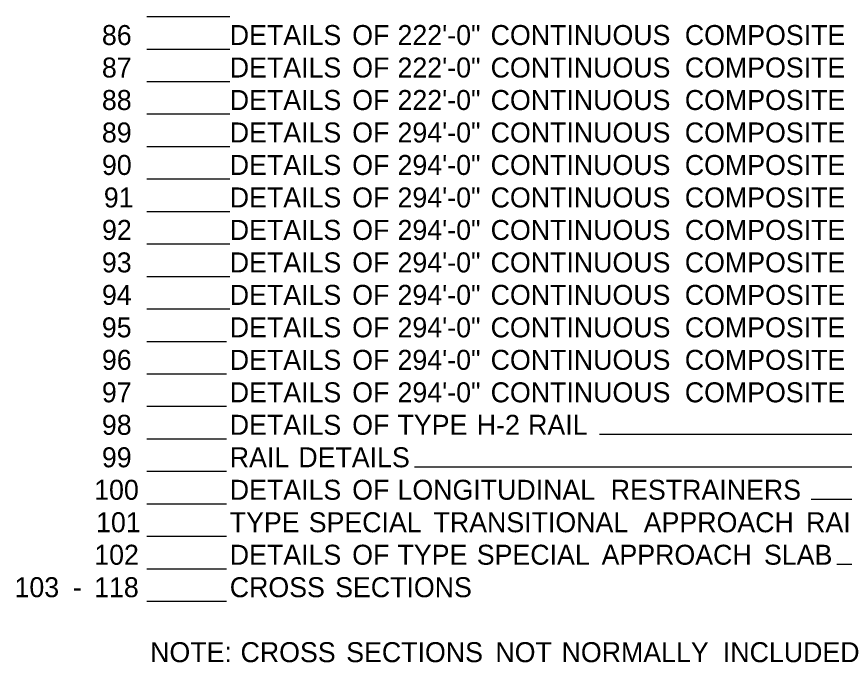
# Model space of a CAD drawing. Extents: x 2 to 32.9, y 0.7 to 21.4.
# Drawn here: x 2.06 to 8.57, y 1.03 to 6.11 of the extents above; entities that cross this region are included whole.
import ezdxf

# ---------------------------------------------------------------- set-up
doc = ezdxf.new("R2010")
doc.units = 0
doc.layers.add('Default', color=7, linetype='Continuous')

msp = doc.modelspace()

# ---------------------------------------------------------------- linework, layer by layer
at = {"layer": 'Default'}
for p, q in [((3.0822, 6.1118), (3.734, 6.1118)), ((3.0822, 5.8562), (3.734, 5.8562)), ((3.0822, 5.8562), (3.7084, 5.8562)), ((3.0822, 5.8562), (3.7084, 5.8562)), ((3.0822, 5.6006), (3.734, 5.6006)), ((3.0822, 5.6006), (3.7084, 5.6006)), ((3.0822, 5.6006), (3.7084, 5.6006)), ((3.0822, 5.3451), (3.734, 5.3451)), ((3.0822, 5.3451), (3.7084, 5.3451)), ((3.0822, 5.3451), (3.7084, 5.3451)), ((3.0822, 5.0895), (3.734, 5.0895)), ((3.0822, 5.0895), (3.7084, 5.0895)), ((3.0822, 5.0895), (3.7084, 5.0895)), ((3.0822, 4.8339), (3.734, 4.8339)), ((3.0822, 4.8339), (3.7084, 4.8339)), ((3.0822, 4.8339), (3.7084, 4.8339)), ((3.0822, 4.5783), (3.734, 4.5783)), ((3.0822, 4.5783), (3.7084, 4.5783)), ((3.0822, 4.5783), (3.7084, 4.5783)), ((3.0822, 4.3227), (3.734, 4.3227)), ((3.0822, 4.3227), (3.7084, 4.3227)), ((3.0822, 4.3227), (3.7084, 4.3227)), ((3.0822, 4.0671), (3.734, 4.0671)), ((3.0822, 4.0671), (3.7084, 4.0671)), ((3.0822, 4.0671), (3.7084, 4.0671)), ((3.0822, 3.8115), (3.734, 3.8115)), ((3.0822, 3.8115), (3.7084, 3.8115)), ((3.0822, 3.8115), (3.7084, 3.8115)), ((3.0822, 3.5559), (3.7084, 3.5559)), ((3.0822, 3.5559), (3.7084, 3.5559)), ((3.0822, 3.3003), (3.7084, 3.3003)), ((3.0822, 3.3003), (3.7084, 3.3003)), ((3.0822, 3.0447), (3.7084, 3.0447)), ((3.0822, 3.0447), (3.7084, 3.0447)), ((6.6412, 2.8243), (13.6355, 2.8243)), ((3.0822, 2.7892), (3.7084, 2.7892)), ((3.0822, 2.7892), (3.7084, 2.7892)), ((5.1864, 2.5687), (13.6355, 2.5687)), ((3.0822, 2.5336), (3.7084, 2.5336)), ((3.0822, 2.5336), (3.7084, 2.5336)), ((8.3055, 2.3131), (13.6355, 2.3131)), ((3.0822, 2.278), (3.7084, 2.278)), ((3.0822, 2.278), (3.7084, 2.278)), ((3.0822, 2.0224), (3.7084, 2.0224)), ((3.0822, 2.0224), (3.7084, 2.0224)), ((3.0822, 1.7668), (3.7084, 1.7668)), ((3.0822, 1.7668), (3.7084, 1.7668)), ((8.5089, 1.8019), (13.6355, 1.8019)), ((3.0822, 1.5112), (3.7084, 1.5112)), ((3.0822, 1.5112), (3.7084, 1.5112))]:
    msp.add_line(p, q, dxfattribs=at)

# ---------------------------------------------------------------- texts
for s, height, p in [('86', 0.15729, (2.7286, 5.8877)), ('86', 0.15729, (2.7286, 5.8877)), ('DETAILS', 0.15729, (3.734, 5.8877)), ('DETAILS', 0.15729, (3.734, 5.8877)), (' OF', 0.15729, (4.6385, 5.8877)), (' OF', 0.15729, (4.6385, 5.8877)), (' 222\'-0"', 0.15729, (4.9947, 5.8877)), (' 222\'-0"', 0.15729, (4.9947, 5.8877)), (' CONTINUOUS', 0.157286, (5.7271, 5.8877)), (' CONTINUOUS', 0.157286, (5.7271, 5.8877)), (' COMPOSITE', 0.15729, (7.2541, 5.8877)), (' COMPOSITE', 0.15729, (7.2541, 5.8877)), ('87', 0.15729, (2.7286, 5.6321)), ('87', 0.15729, (2.7286, 5.6321)), ('DETAILS', 0.15729, (3.734, 5.6321)), ('DETAILS', 0.15729, (3.734, 5.6321)), (' OF', 0.15729, (4.6385, 5.6321)), (' OF', 0.15729, (4.6385, 5.6321)), (' 222\'-0"', 0.15729, (4.9947, 5.6321)), (' 222\'-0"', 0.15729, (4.9947, 5.6321)), (' CONTINUOUS', 0.157286, (5.7271, 5.6321)), (' CONTINUOUS', 0.157286, (5.7271, 5.6321)), (' COMPOSITE', 0.15729, (7.2541, 5.6321)), (' COMPOSITE', 0.15729, (7.2541, 5.6321)), ('88', 0.15729, (2.7285, 5.3765)), ('88', 0.15729, (2.7285, 5.3765)), ('DETAILS', 0.15729, (3.734, 5.3765)), ('DETAILS', 0.15729, (3.734, 5.3765)), (' OF', 0.15729, (4.6385, 5.3765)), (' OF', 0.15729, (4.6385, 5.3765)), (' 222\'-0"', 0.15729, (4.9947, 5.3765)), (' 222\'-0"', 0.15729, (4.9947, 5.3765)), (' CONTINUOUS', 0.157286, (5.7271, 5.3765)), (' CONTINUOUS', 0.157286, (5.7271, 5.3765)), (' COMPOSITE', 0.15729, (7.2541, 5.3765)), (' COMPOSITE', 0.15729, (7.2541, 5.3765)), ('89', 0.15729, (2.7285, 5.1209)), ('89', 0.15729, (2.7285, 5.1209)), ('DETAILS', 0.15729, (3.734, 5.1209)), ('DETAILS', 0.15729, (3.734, 5.1209)), (' OF', 0.15729, (4.6385, 5.1209)), (' OF', 0.15729, (4.6385, 5.1209)), (' 294\'-0"', 0.15729, (4.9947, 5.1209)), (' 294\'-0"', 0.15729, (4.9947, 5.1209)), (' CONTINUOUS', 0.157286, (5.7271, 5.1209)), (' CONTINUOUS', 0.157286, (5.7271, 5.1209)), (' COMPOSITE', 0.15729, (7.2541, 5.1209)), (' COMPOSITE', 0.15729, (7.2541, 5.1209)), ('90', 0.15729, (2.7289, 4.8653)), ('90', 0.15729, (2.7289, 4.8653)), ('DETAILS', 0.15729, (3.734, 4.8653)), ('DETAILS', 0.15729, (3.734, 4.8653)), (' OF', 0.15729, (4.6385, 4.8653)), (' OF', 0.15729, (4.6385, 4.8653)), (' 294\'-0"', 0.15729, (4.9947, 4.8653)), (' 294\'-0"', 0.15729, (4.9947, 4.8653)), (' CONTINUOUS', 0.157286, (5.7271, 4.8653)), (' CONTINUOUS', 0.157286, (5.7271, 4.8653)), (' COMPOSITE', 0.15729, (7.2541, 4.8653)), (' COMPOSITE', 0.15729, (7.2541, 4.8653)), ('91', 0.15729, (2.7438, 4.6097)), ('91', 0.15729, (2.7438, 4.6097)), ('DETAILS', 0.15729, (3.734, 4.6097)), ('DETAILS', 0.15729, (3.734, 4.6097)), (' OF', 0.15729, (4.6385, 4.6097)), (' OF', 0.15729, (4.6385, 4.6097)), (' 294\'-0"', 0.15729, (4.9947, 4.6097)), (' 294\'-0"', 0.15729, (4.9947, 4.6097)), (' CONTINUOUS', 0.157286, (5.7271, 4.6097)), (' CONTINUOUS', 0.157286, (5.7271, 4.6097)), (' COMPOSITE', 0.15729, (7.2541, 4.6097)), (' COMPOSITE', 0.15729, (7.2541, 4.6097)), ('92', 0.15729, (2.7294, 4.3542)), ('92', 0.15729, (2.7294, 4.3542)), ('DETAILS', 0.15729, (3.734, 4.3542)), ('DETAILS', 0.15729, (3.734, 4.3542)), (' OF', 0.15729, (4.6385, 4.3542)), (' OF', 0.15729, (4.6385, 4.3542)), (' 294\'-0"', 0.15729, (4.9947, 4.3542)), (' 294\'-0"', 0.15729, (4.9947, 4.3542)), (' CONTINUOUS', 0.157286, (5.7271, 4.3542)), (' CONTINUOUS', 0.157286, (5.7271, 4.3542)), (' COMPOSITE', 0.15729, (7.2541, 4.3542)), (' COMPOSITE', 0.15729, (7.2541, 4.3542)), ('93', 0.15729, (2.7286, 4.0986)), ('93', 0.15729, (2.7286, 4.0986)), ('DETAILS', 0.15729, (3.734, 4.0986)), ('DETAILS', 0.15729, (3.734, 4.0986)), (' OF', 0.15729, (4.6385, 4.0986)), (' OF', 0.15729, (4.6385, 4.0986)), (' 294\'-0"', 0.15729, (4.9947, 4.0986)), (' 294\'-0"', 0.15729, (4.9947, 4.0986)), (' CONTINUOUS', 0.157286, (5.7271, 4.0986)), (' CONTINUOUS', 0.157286, (5.7271, 4.0986)), (' COMPOSITE', 0.15729, (7.2541, 4.0986)), (' COMPOSITE', 0.15729, (7.2541, 4.0986)), ('94', 0.15729, (2.729, 3.843)), ('94', 0.15729, (2.729, 3.843)), ('DETAILS', 0.15729, (3.734, 3.843)), ('DETAILS', 0.15729, (3.734, 3.843)), (' OF', 0.15729, (4.6385, 3.843)), (' OF', 0.15729, (4.6385, 3.843)), (' 294\'-0"', 0.15729, (4.9947, 3.843)), (' 294\'-0"', 0.15729, (4.9947, 3.843)), (' CONTINUOUS', 0.157286, (5.7271, 3.843)), (' CONTINUOUS', 0.157286, (5.7271, 3.843)), (' COMPOSITE', 0.15729, (7.2541, 3.843)), (' COMPOSITE', 0.15729, (7.2541, 3.843)), ('95', 0.15729, (2.728, 3.5874)), ('95', 0.15729, (2.728, 3.5874)), ('DETAILS', 0.15729, (3.734, 3.5874)), ('DETAILS', 0.15729, (3.734, 3.5874)), (' OF', 0.15729, (4.6385, 3.5874)), (' OF', 0.15729, (4.6385, 3.5874)), (' 294\'-0"', 0.15729, (4.9947, 3.5874)), (' 294\'-0"', 0.15729, (4.9947, 3.5874)), (' CONTINUOUS', 0.157286, (5.7271, 3.5874)), (' CONTINUOUS', 0.157286, (5.7271, 3.5874)), (' COMPOSITE', 0.15729, (7.2541, 3.5874)), (' COMPOSITE', 0.15729, (7.2541, 3.5874)), ('96', 0.15729, (2.7286, 3.3318)), ('96', 0.15729, (2.7286, 3.3318)), ('DETAILS', 0.15729, (3.734, 3.3318)), ('DETAILS', 0.15729, (3.734, 3.3318)), (' OF', 0.15729, (4.6385, 3.3318)), (' OF', 0.15729, (4.6385, 3.3318)), (' 294\'-0"', 0.15729, (4.9947, 3.3318)), (' 294\'-0"', 0.15729, (4.9947, 3.3318)), (' CONTINUOUS', 0.157286, (5.7271, 3.3318)), (' CONTINUOUS', 0.157286, (5.7271, 3.3318)), (' COMPOSITE', 0.15729, (7.2541, 3.3318)), (' COMPOSITE', 0.15729, (7.2541, 3.3318)), ('97', 0.15729, (2.7286, 3.0762)), ('97', 0.15729, (2.7286, 3.0762)), ('DETAILS', 0.15729, (3.734, 3.0762)), ('DETAILS', 0.15729, (3.734, 3.0762)), (' OF', 0.15729, (4.6385, 3.0762)), (' OF', 0.15729, (4.6385, 3.0762)), (' 294\'-0"', 0.15729, (4.9947, 3.0762)), (' 294\'-0"', 0.15729, (4.9947, 3.0762)), (' CONTINUOUS', 0.157286, (5.7271, 3.0762)), (' CONTINUOUS', 0.157286, (5.7271, 3.0762)), (' COMPOSITE', 0.15729, (7.2541, 3.0762)), (' COMPOSITE', 0.15729, (7.2541, 3.0762)), ('98', 0.15729, (2.7285, 2.8206)), ('98', 0.15729, (2.7285, 2.8206)), ('DETAILS', 0.15729, (3.734, 2.8206)), ('DETAILS', 0.15729, (3.734, 2.8206)), (' OF', 0.15729, (4.6385, 2.8206)), (' OF', 0.15729, (4.6385, 2.8206)), (' TYPE', 0.15729, (4.9947, 2.8206)), (' TYPE', 0.15729, (4.9947, 2.8206)), (' H-2', 0.15729, (5.618, 2.8206)), (' H-2', 0.15729, (5.618, 2.8206)), (' RAIL', 0.15729, (6.0214, 2.8206)), (' RAIL', 0.15729, (6.0214, 2.8206)), ('99', 0.15729, (2.7285, 2.565)), ('99', 0.15729, (2.7285, 2.565)), ('RAIL', 0.15729, (3.734, 2.565)), ('RAIL', 0.15729, (3.734, 2.565)), (' DETAILS', 0.15729, (4.2147, 2.565)), (' DETAILS', 0.15729, (4.2147, 2.565)), ('100', 0.15729, (2.6678, 2.3094)), ('100', 0.15729, (2.6678, 2.3094)), ('DETAILS', 0.15729, (3.734, 2.3094)), ('DETAILS', 0.15729, (3.734, 2.3094)), (' OF', 0.15729, (4.6385, 2.3094)), (' OF', 0.15729, (4.6385, 2.3094)), (' LONGITUDINAL', 0.157286, (4.9947, 2.3094)), (' LONGITUDINAL', 0.157286, (4.9947, 2.3094)), (' RESTRAINERS', 0.157286, (6.6719, 2.3094)), (' RESTRAINERS', 0.157286, (6.6719, 2.3094)), ('101', 0.15729, (2.6827, 2.0538)), ('101', 0.15729, (2.6827, 2.0538)), ('TYPE', 0.15729, (3.734, 2.0538)), ('TYPE', 0.15729, (3.734, 2.0538)), (' SPECIAL', 0.15729, (4.2963, 2.0538)), (' SPECIAL', 0.15729, (4.2963, 2.0538)), (' TRANSITIONAL', 0.157286, (5.2779, 2.0538)), (' TRANSITIONAL', 0.157286, (5.2779, 2.0538)), (' APPROACH', 0.15729, (6.9309, 2.0538)), (' APPROACH', 0.15729, (6.9309, 2.0538)), (' RAILING', 0.15729, (8.2078, 2.0538)), (' RAILING', 0.15729, (8.2078, 2.0538)), ('102', 0.15729, (2.6684, 1.7982)), ('102', 0.15729, (2.6684, 1.7982)), ('DETAILS', 0.15729, (3.734, 1.7982)), ('DETAILS', 0.15729, (3.734, 1.7982)), (' OF', 0.15729, (4.6385, 1.7982)), (' OF', 0.15729, (4.6385, 1.7982)), (' TYPE', 0.15729, (4.9947, 1.7982)), (' TYPE', 0.15729, (4.9947, 1.7982)), (' SPECIAL', 0.15729, (5.618, 1.7982)), (' SPECIAL', 0.15729, (5.618, 1.7982)), (' APPROACH', 0.15729, (6.5996, 1.7982)), (' APPROACH', 0.15729, (6.5996, 1.7982)), (' SLAB', 0.15729, (7.8765, 1.7982)), (' SLAB', 0.15729, (7.8765, 1.7982)), ('103', 0.15729, (2.0413, 1.5427)), ('103', 0.15729, (2.0413, 1.5427)), ('118', 0.15729, (2.6674, 1.5427)), ('118', 0.15729, (2.6674, 1.5427)), ('CROSS', 0.15729, (3.734, 1.5427)), ('CROSS', 0.15729, (3.734, 1.5427)), (' SECTIONS', 0.15729, (4.5041, 1.5427)), (' SECTIONS', 0.15729, (4.5041, 1.5427)), ('-', 0.1573, (2.4995, 1.5427)), ('-', 0.1573, (2.4995, 1.5427)), ('NOTE:', 0.15729, (3.1078, 1.0315)), ('NOTE:', 0.15729, (3.1078, 1.0315)), (' CROSS', 0.15729, (3.7602, 1.0315)), (' CROSS', 0.15729, (3.7602, 1.0315)), (' SECTIONS', 0.15729, (4.5913, 1.0315)), (' SECTIONS', 0.15729, (4.5913, 1.0315)), (' NOT', 0.15729, (5.7644, 1.0315)), (' NOT', 0.15729, (5.7644, 1.0315)), (' NORMALLY', 0.15729, (6.2849, 1.0315)), (' NORMALLY', 0.15729, (6.2849, 1.0315)), (' INCLUDED', 0.15729, (7.5533, 1.0315)), (' INCLUDED', 0.15729, (7.5533, 1.0315))]:
    msp.add_text(s, height=height, dxfattribs=at).set_placement(p)

doc.saveas('drawing.dxf')
